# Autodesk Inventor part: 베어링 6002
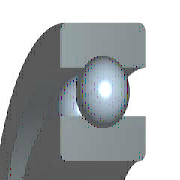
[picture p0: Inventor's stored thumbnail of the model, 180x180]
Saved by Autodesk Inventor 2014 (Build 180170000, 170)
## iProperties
IsCustomPart: 0
Created: 2012-02
Part Number: 베어링 6002
Material: 강철, 연강
Description: 깊은 그루브 볼 베어링
Document SubType Name: Modeling
Standard: KS B 2023
Designer: mduedu
Standards Organization: KS
Language: ko-KR
Size Designation: 6002 - 15 x 32 x 9
Categories: <MemberInstance><Categories><Category DisplayName="샤프트 부품" InternalName="7f7aeb1f-a693-4053-b835-cee3144e0d98" Mnemonic="SHFT"><Category DisplayName="베어링" Inter
Density: 1 g/cm^3
Appearance: Yellow
Author: mduedu
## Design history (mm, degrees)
sketch "스케치" dims "d0" = 4.42 (= -0.26 x WD + 0.26 x BD)
  geometry: L1 (2.29, 11.75)-(6.71, 11.75); L2 (4.5, 11.75)-(4.5, 9.54); L3 (4.5, 11.75)-(4.5, 13.96); L4 (2.858, 10.271)-(0, 10.271); L5 (0, 7.5)-(9, 7.5); L6 (2.858, 13.229)-(0, 13.229); L7 (0, 16)-(9, 16); L8 (9, 7.5)-(9, 10.271); L9 (6.142, 10.271)-(9, 10.271); L10 (6.142, 13.229)-(9, 13.229); L11 (9, 16)-(9, 13.229); L12 (-1.4, 0)-(8.4, 0) reference; L13 (0, -0.3)-(0, 5.3) reference
  constraints: 22 end point, 4 point on line, 2 collinear, 2 perpendicular, 2 symmetric about line, 1 midpoint, 1 parallel, 14 other
  dimensions: "d9" = 15 diameter of L5 L12 (= WD); "d11" = 32 diameter of L7 L12 (= BD); "d12" = 9 distance between parallel lines of L8 L13 (= KB); "d13" = 20.542 diameter of L9 L12 (= 0.326 x BD + 0.674 x WD)
revolve "본체" stored, may be unused: angle "d6" = 90 deg
revolve "볼" stored, may be unused: angle "d7" = 90 deg
pattern_circular "IDS_ARRAYBALL[SIMPL:T]" dims angle "d3" = 360 deg
body "Solid1"
fillet "모깎기1" dims "d1" = 0.3 (= KRS)
other parameters: "WD" = 15 [user parameter; used in 5 equation terms], "BD" = 32 [user parameter; used in 5 equation terms], "KB" = 9 [user parameter; used in 1 equation term], "KRS" = 0.3 [user parameter; used in 1 equation term], "d4" = 0, "d5" = 0, "d8" = 0, "d14" = 0, "d15" = 0, "BBA" = 0 [user parameter], "BC0" = 2850000 [user parameter], "BC" = 5590000 [user parameter], "BR" = 16 (= 0.5 x BD) [user parameter], "WR" = 7.5 (= 0.5 x WD) [user parameter]
